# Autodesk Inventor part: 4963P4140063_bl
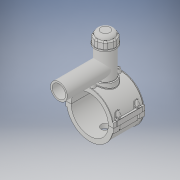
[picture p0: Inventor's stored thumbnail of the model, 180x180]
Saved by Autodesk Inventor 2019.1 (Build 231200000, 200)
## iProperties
Created: 2017-07
Part Number: 4963P4140063_bl
Material: Generic
Document SubType Name: Modeling
Designer: KIM
Density: 1 g/cm^3
Appearance: Default
Author: KIM
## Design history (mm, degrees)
derived "4963P4.ipt"
feature "Solid1::4963P4.ipt" dims "ScaleForDerivedMember" = 10
feature "Solid2::4963P4.ipt" dims "ScaleForDerivedMember" = 10
feature "Solid3::4963P4.ipt" dims "ScaleForDerivedMember" = 10
tag "TaggingFeature1"
body "Solid1"
body "Solid2"
body "Solid3"
other parameters: "d3" = 35 [user parameter], "d4" = 118 [user parameter], "d5" = 0 [user parameter], "d6" = 0.1 [user parameter], "d8" = 0 [user parameter], "d19" = 6 [user parameter], "d20" = 6 [user parameter], "d21" = 70.8 [user parameter], "d23" = 0 [user parameter], "d24" = 35.4 [user parameter], "d26" = 0 [user parameter], "d27" = 3 [user parameter], "d28" = 3 [user parameter], "d29" = 3 [user parameter], "d30" = 46.66667 [user parameter], "d31" = 6 [user parameter], "d32" = 0 [user parameter], "d33" = 0 [user parameter], "d34" = 0.6 [user parameter], "d40" = 88.816 [user parameter], "d41" = 77 [user parameter], "d43" = 0 [user parameter], "d45" = 0 [user parameter], "d47" = 156.2 [user parameter], "d70" = 15 [user parameter], "d72" = 0 [user parameter], "d73" = 6 [user parameter], "d75" = 5 [user parameter], "d76" = 0 [user parameter], "d77" = 7 [user parameter], "d79" = 15 [user parameter], "d80" = 47.2 [user parameter], "d82" = 5 deg [user parameter], "d84" = 4 [user parameter], "d85" = 14 [user parameter], "d86" = 0 [user parameter], "d87" = 3 [user parameter], "d88" = 0 [user parameter], "d89" = 1 [user parameter], "d90" = 1 [user parameter], "d91" = 94.4 [user parameter], "d92" = 0 [user parameter], "d93" = 0.5 [user parameter], "d94" = 73.68421 [user parameter], "d96" = 174.216 [user parameter], "d97" = 2.36 [user parameter], "d98" = 0 [user parameter], "d102" = 1.4 [user parameter], "d120" = 140 deg [user parameter], "d121" = 24.228 [user parameter], "d122" = 20 deg [user parameter], "d123" = 341.6 [user parameter], "d124" = 102.48 [user parameter], "d126" = 0 [user parameter], "d143" = 144.2 [user parameter], "d145" = 23.69231 [user parameter], "d149" = 2.1 [user parameter], "d150" = 26.06154 [user parameter], "d153" = 118 [user parameter], "d154" = 0 [user parameter], "d156" = 85.4 [user parameter], "d157" = 160 deg [user parameter], "d159" = 6.16 [user parameter], "d161" = 2.1 [user parameter], "d162" = 70.8 [user parameter], "d163" = 0 [user parameter], "d167" = 14 [user parameter], "d168" = 83.31707 [user parameter], "d170" = 3.75 [user parameter], "d172" = 0 [user parameter], "d173" = 1 [user parameter], "d176" = 20 deg [user parameter], "d177" = 9.8 [user parameter], "d178" = 30.8 [user parameter], "d180" = 0 [user parameter], "d183" = 12.32 [user parameter], "d184" = 7.84 [user parameter], "d185" = 38.35 [user parameter], "d186" = 38.35 [user parameter], "d187" = 85.4 [user parameter], "d188" = 9.24 [user parameter], "d189" = 9.8 [user parameter], "d190" = 0 [user parameter], "d191" = 128.1 [user parameter], "d193" = 8 [user parameter], "d194" = 4.13 [user parameter], "d195" = 90 deg [user parameter], "d197" = 0 [user parameter], "d199" = 0 [user parameter], "d200" = 15.4 [user parameter], "d202" = 0 [user parameter], "d203" = 177 [user parameter], "d204" = 73.15 [user parameter], "d205" = 53.9 [user parameter], "d206" = 65.45 [user parameter], "d207" = 132.75 [user parameter], "d208" = 138.06 [user parameter], "d209" = 164.61 [user parameter], "d210" = 66.22 [user parameter], "d211" = 77 [user parameter], "d212" = 61.6 [user parameter], "d213" = 29.25 [user parameter], "d216" = 0 [user parameter], "d217" = 14 [user parameter], "d218" = 14 [user parameter], "d219" = 2.8 [user parameter], "d224" = 0 [user parameter], "d225" = 64 [user parameter], "d226" = 63 [user parameter], "d227" = 50.4 [user parameter], "d228" = 175 [user parameter], "d230" = 5.6 [user parameter], "L_" = 118 [user parameter], "d_t" = 6 [user parameter], "H_2" = 177 [user parameter], "H_1" = 64 [user parameter], "d_1" = 63 [user parameter], "H_" = 175 [user parameter], "d1" = 170.8 [user parameter], "d148" = 2.1 [user parameter]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
